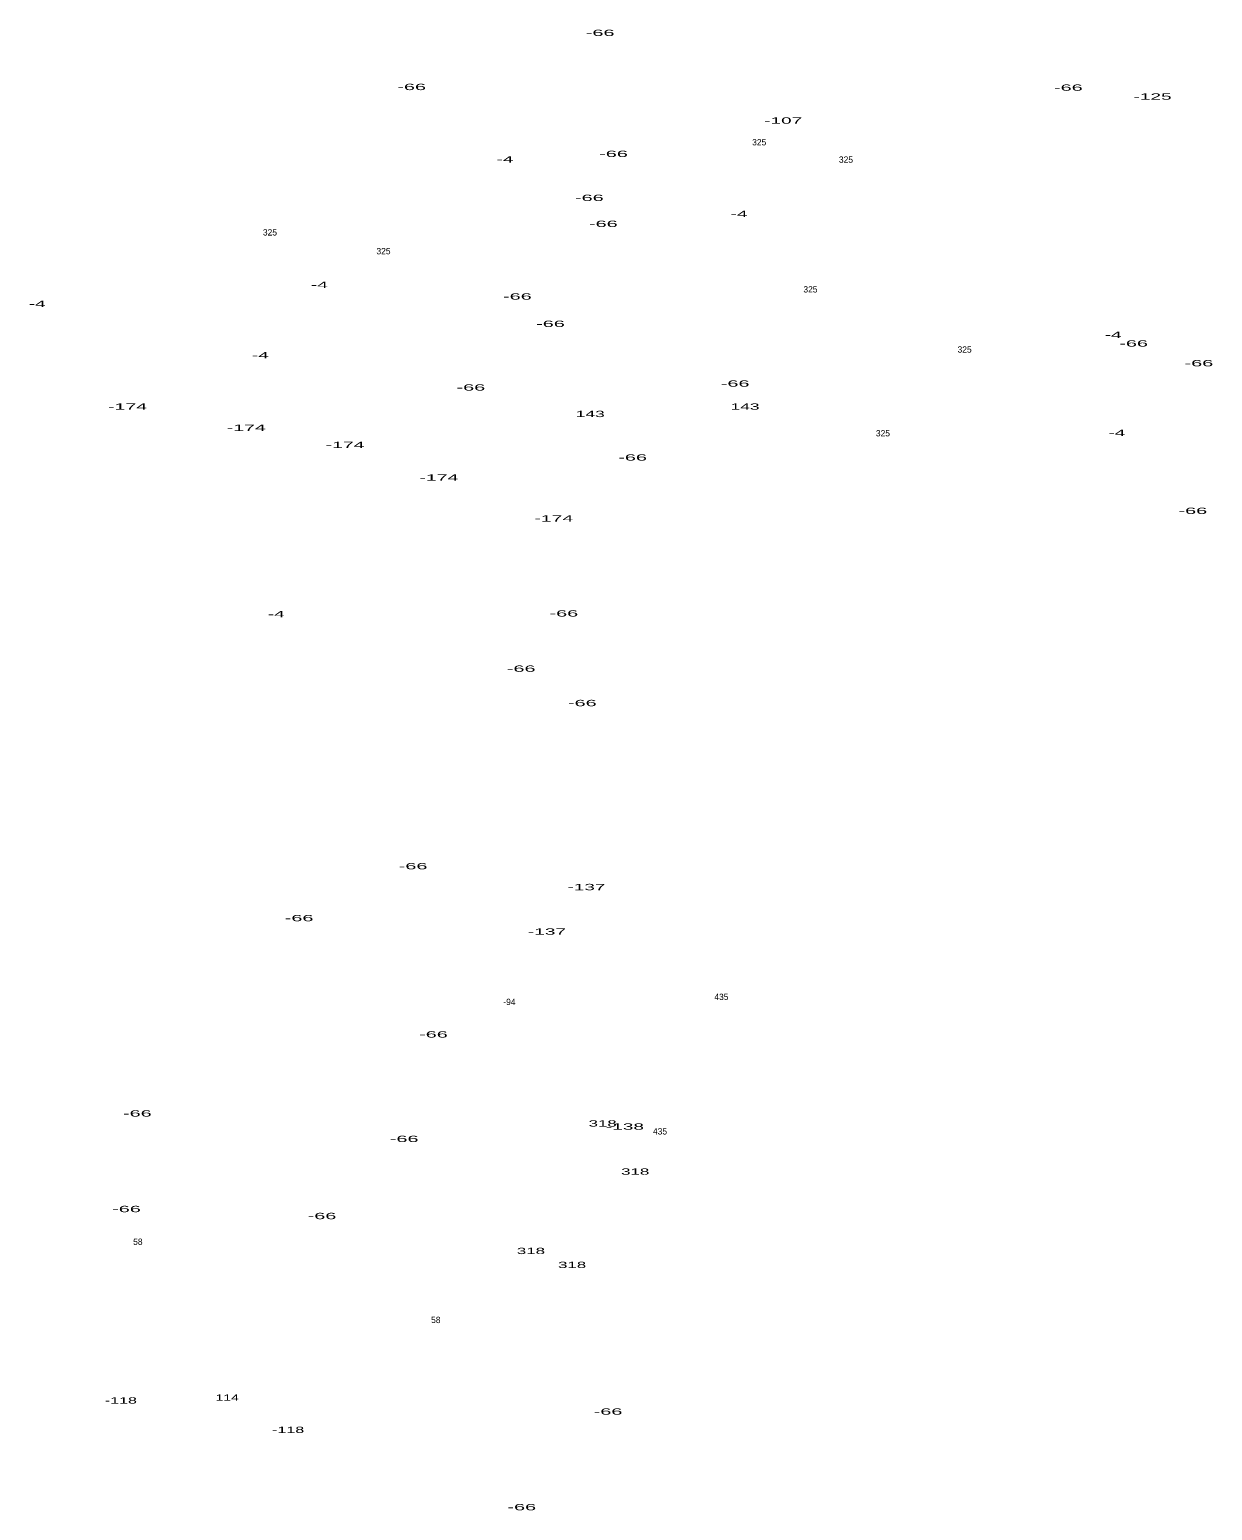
# Model space of a CAD drawing. Extents: x -662280 to -658689, y -991723 to -987042.
# Drawn here: x -660885 to -660136, y -991306 to -990368 of the extents above; entities that cross this region are included whole.
import ezdxf
from ezdxf.enums import TextEntityAlignment as Align

# ---------------------------------------------------------------- set-up
doc = ezdxf.new("R2010")
doc.units = 0
doc.header["$LTSCALE"] = 1.6
doc.layers.add('24', color=7, linetype='Continuous')

msp = doc.modelspace()

# ---------------------------------------------------------------- texts
at = {"layer": '24'}
for s, width, p in [('-66', 2.35, (-660523.443, -990371.93)), ('-66', 2.35, (-660642.813, -990406.17)), ('-66', 2.35, (-660226.943, -990406.59)), ('-125', 2.25, (-660173.581, -990412.24)), ('-107', 2.25, (-660407.531, -990427.45)), ('-4', 2.25, (-660583.73, -990452.02)), ('-66', 2.35, (-660514.973, -990448.54)), ('-66', 2.35, (-660530.293, -990476.39)), ('-4', 2.25, (-660435.48, -990486.59)), ('-66', 2.35, (-660521.423, -990492.84)), ('-4', 2.25, (-660701.23, -990531.44)), ('-4', 2.25, (-660879.94, -990543.49)), ('-66', 2.35, (-660575.863, -990538.84)), ('-66', 2.35, (-660554.893, -990556.15)), ('-4', 2.25, (-660198.58, -990563.11)), ('-66', 2.35, (-660185.603, -990568.59)), ('-4', 2.25, (-660738.66, -990576.11)), ('-66', 2.35, (-660144.263, -990581.1)), ('-66', 2.35, (-660605.303, -990596.47)), ('-66', 2.35, (-660437.943, -990593.99)), ('-174', 2.3, (-660822.731, -990608.6)), ('143', 2.05, (-660431.683, -990608.57)), ('143', 2.05, (-660529.713, -990613.24)), ('-174', 2.3, (-660747.531, -990621.95)), ('-4', 2.25, (-660196.21, -990625.21)), ('-174', 2.3, (-660685.001, -990632.87)), ('-66', 2.35, (-660502.873, -990640.8)), ('-174', 2.3, (-660625.571, -990653.51)), ('-66', 2.35, (-660148.103, -990674.59)), ('-174', 2.3, (-660552.801, -990679.4)), ('-4', 2.25, (-660728.57, -990739.99)), ('-66', 2.35, (-660546.423, -990739.54)), ('-66', 2.35, (-660573.443, -990774.53)), ('-66', 2.35, (-660534.733, -990796.31)), ('-66', 2.35, (-660641.903, -990899.61)), ('-137', 2.25, (-660532.135, -990912.82)), ('-66', 2.35, (-660714.093, -990932.49)), ('-137', 2.25, (-660557.115, -990941.01)), ('-66', 2.35, (-660629.003, -991006.14)), ('-66', 2.35, (-660816.523, -991056.18)), ('318', 2, (-660521.857, -991062.51)), ('-138', 2.25, (-660507.731, -991064.48)), ('-66', 2.35, (-660647.553, -991072.31)), ('318', 2, (-660501.247, -991093)), ('-66', 2.35, (-660823.383, -991116.71)), ('-66', 2.35, (-660699.573, -991121.14)), ('318', 2, (-660567.267, -991143.25)), ('318', 2, (-660541.197, -991152.08)), ('-118', 1.9, (-660826.957, -991237.93)), ('114', 1.65, (-660759.619, -991236.15)), ('-66', 2.35, (-660518.443, -991244.96)), ('-118', 1.9, (-660721.027, -991256.53)), ('-66', 2.35, (-660573.083, -991305.49))]:
    msp.add_text(s, height=4, dxfattribs=dict(at, width=width)).set_placement(p, align=Align.CENTER)
for s, p in [('325', (-660422.717, -990441.17)), ('325', (-660367.777, -990452.2)), ('325', (-660732.557, -990498.25)), ('325', (-660660.647, -990510.14)), ('325', (-660390.267, -990534.33)), ('325', (-660292.647, -990572.42)), ('325', (-660344.367, -990625.47)), ('-94', (-660580.895, -990985.53)), ('435', (-660446.651, -990982.36)), ('435', (-660485.531, -991067.53)), ('58', (-660816.187, -991137.42)), ('58', (-660627.507, -991186.94))]:
    msp.add_text(s, height=4, dxfattribs=at).set_placement(p, align=Align.CENTER)

doc.saveas('drawing.dxf')
